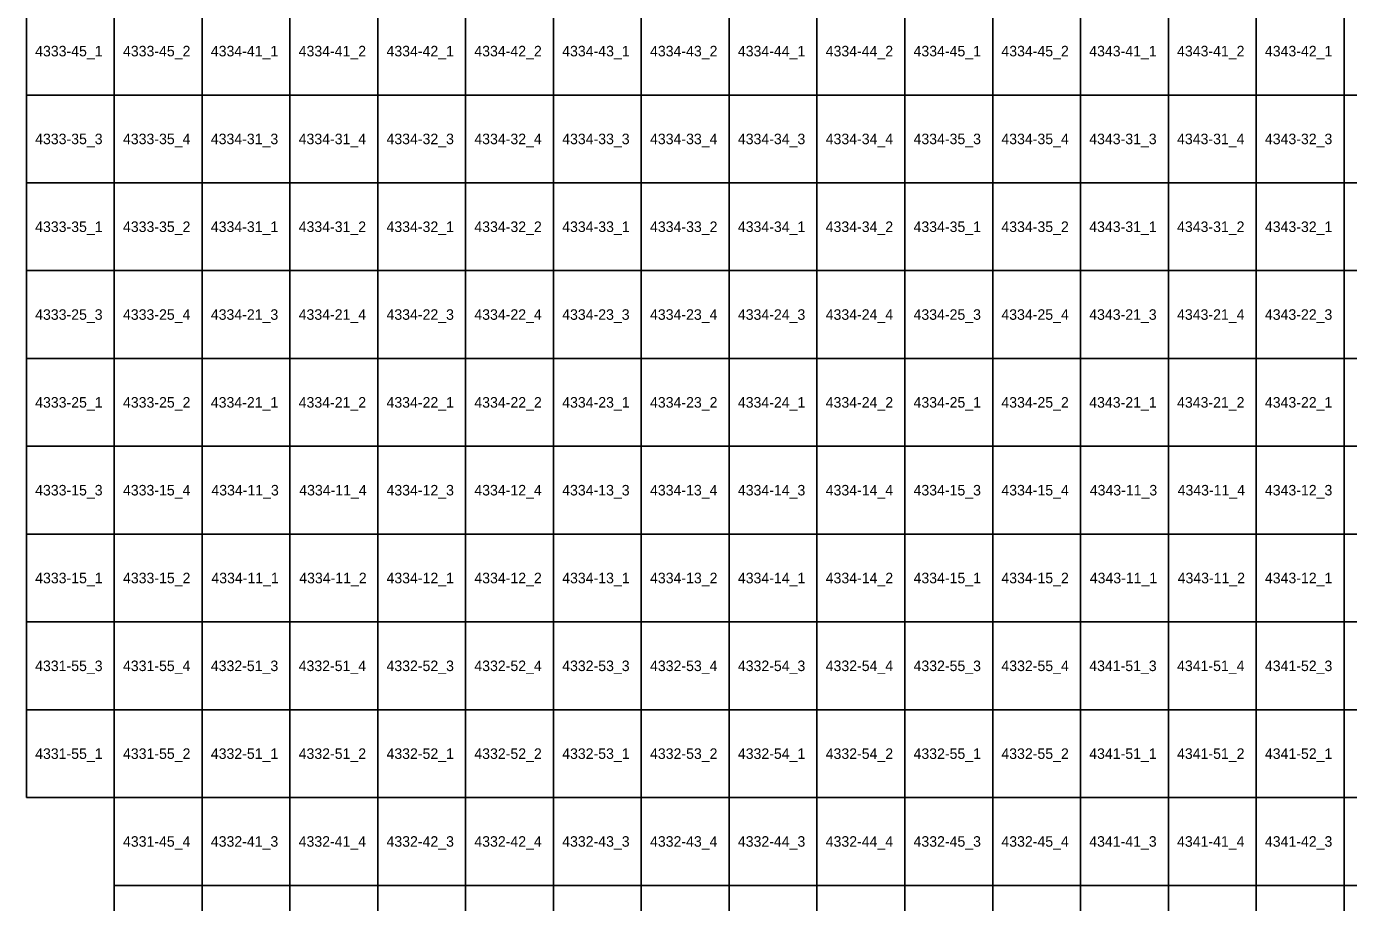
# Model space of a CAD drawing. Extents: x 312500 to 765000, y 172500 to 440000.
# Drawn here: x 520000 to 557629, y 367011 to 391952 of the extents above; entities that cross this region are included whole.
import ezdxf

# ---------------------------------------------------------------- set-up
doc = ezdxf.new("R2010")
doc.units = 0
doc.layers.add('Topo5_ramis_TKS2025', color=7, linetype='Continuous')
doc.layers.add('Topo5_ramis_TKS2025_Nr', color=7, linetype='Continuous')

msp = doc.modelspace()

# ---------------------------------------------------------------- linework, layer by layer
at = {"layer": 'Topo5_ramis_TKS2025'}
for points in [[(520000, 390000), (520000, 392500), (522500, 392500), (522500, 390000), (520000, 390000)], [(522500, 390000), (522500, 392500), (525000, 392500), (525000, 390000), (522500, 390000)], [(525000, 390000), (525000, 392500), (527500, 392500), (527500, 390000), (525000, 390000)], [(527500, 390000), (527500, 392500), (530000, 392500), (530000, 390000), (527500, 390000)], [(530000, 390000), (530000, 392500), (532500, 392500), (532500, 390000), (530000, 390000)], [(532500, 390000), (532500, 392500), (535000, 392500), (535000, 390000), (532500, 390000)], [(535000, 390000), (535000, 392500), (537500, 392500), (537500, 390000), (535000, 390000)], [(537500, 390000), (537500, 392500), (540000, 392500), (540000, 390000), (537500, 390000)], [(540000, 390000), (540000, 392500), (542500, 392500), (542500, 390000), (540000, 390000)], [(542500, 390000), (542500, 392500), (545000, 392500), (545000, 390000), (542500, 390000)], [(545000, 390000), (545000, 392500), (547500, 392500), (547500, 390000), (545000, 390000)], [(547500, 390000), (547500, 392500), (550000, 392500), (550000, 390000), (547500, 390000)], [(550000, 390000), (550000, 392500), (552500, 392500), (552500, 390000), (550000, 390000)], [(552500, 390000), (552500, 392500), (555000, 392500), (555000, 390000), (552500, 390000)], [(555000, 390000), (555000, 392500), (557500, 392500), (557500, 390000), (555000, 390000)], [(557500, 390000), (557500, 392500), (560000, 392500), (560000, 390000), (557500, 390000)], [(520000, 387500), (520000, 390000), (522500, 390000), (522500, 387500), (520000, 387500)], [(522500, 387500), (522500, 390000), (525000, 390000), (525000, 387500), (522500, 387500)], [(525000, 387500), (525000, 390000), (527500, 390000), (527500, 387500), (525000, 387500)], [(527500, 387500), (527500, 390000), (530000, 390000), (530000, 387500), (527500, 387500)], [(530000, 387500), (530000, 390000), (532500, 390000), (532500, 387500), (530000, 387500)], [(532500, 387500), (532500, 390000), (535000, 390000), (535000, 387500), (532500, 387500)], [(535000, 387500), (535000, 390000), (537500, 390000), (537500, 387500), (535000, 387500)], [(537500, 387500), (537500, 390000), (540000, 390000), (540000, 387500), (537500, 387500)], [(540000, 387500), (540000, 390000), (542500, 390000), (542500, 387500), (540000, 387500)], [(542500, 387500), (542500, 390000), (545000, 390000), (545000, 387500), (542500, 387500)], [(545000, 387500), (545000, 390000), (547500, 390000), (547500, 387500), (545000, 387500)], [(547500, 387500), (547500, 390000), (550000, 390000), (550000, 387500), (547500, 387500)], [(550000, 387500), (550000, 390000), (552500, 390000), (552500, 387500), (550000, 387500)], [(552500, 387500), (552500, 390000), (555000, 390000), (555000, 387500), (552500, 387500)], [(555000, 387500), (555000, 390000), (557500, 390000), (557500, 387500), (555000, 387500)], [(557500, 387500), (557500, 390000), (560000, 390000), (560000, 387500), (557500, 387500)], [(520000, 385000), (520000, 387500), (522500, 387500), (522500, 385000), (520000, 385000)], [(522500, 385000), (522500, 387500), (525000, 387500), (525000, 385000), (522500, 385000)], [(525000, 385000), (525000, 387500), (527500, 387500), (527500, 385000), (525000, 385000)], [(527500, 385000), (527500, 387500), (530000, 387500), (530000, 385000), (527500, 385000)], [(530000, 385000), (530000, 387500), (532500, 387500), (532500, 385000), (530000, 385000)], [(532500, 385000), (532500, 387500), (535000, 387500), (535000, 385000), (532500, 385000)], [(535000, 385000), (535000, 387500), (537500, 387500), (537500, 385000), (535000, 385000)], [(537500, 385000), (537500, 387500), (540000, 387500), (540000, 385000), (537500, 385000)], [(540000, 385000), (540000, 387500), (542500, 387500), (542500, 385000), (540000, 385000)], [(542500, 385000), (542500, 387500), (545000, 387500), (545000, 385000), (542500, 385000)], [(545000, 385000), (545000, 387500), (547500, 387500), (547500, 385000), (545000, 385000)], [(547500, 385000), (547500, 387500), (550000, 387500), (550000, 385000), (547500, 385000)], [(550000, 385000), (550000, 387500), (552500, 387500), (552500, 385000), (550000, 385000)], [(552500, 385000), (552500, 387500), (555000, 387500), (555000, 385000), (552500, 385000)], [(555000, 385000), (555000, 387500), (557500, 387500), (557500, 385000), (555000, 385000)], [(557500, 385000), (557500, 387500), (560000, 387500), (560000, 385000), (557500, 385000)], [(520000, 382500), (520000, 385000), (522500, 385000), (522500, 382500), (520000, 382500)], [(522500, 382500), (522500, 385000), (525000, 385000), (525000, 382500), (522500, 382500)], [(525000, 382500), (525000, 385000), (527500, 385000), (527500, 382500), (525000, 382500)], [(527500, 382500), (527500, 385000), (530000, 385000), (530000, 382500), (527500, 382500)], [(530000, 382500), (530000, 385000), (532500, 385000), (532500, 382500), (530000, 382500)], [(532500, 382500), (532500, 385000), (535000, 385000), (535000, 382500), (532500, 382500)], [(535000, 382500), (535000, 385000), (537500, 385000), (537500, 382500), (535000, 382500)], [(537500, 382500), (537500, 385000), (540000, 385000), (540000, 382500), (537500, 382500)], [(540000, 382500), (540000, 385000), (542500, 385000), (542500, 382500), (540000, 382500)], [(542500, 382500), (542500, 385000), (545000, 385000), (545000, 382500), (542500, 382500)], [(545000, 382500), (545000, 385000), (547500, 385000), (547500, 382500), (545000, 382500)], [(547500, 382500), (547500, 385000), (550000, 385000), (550000, 382500), (547500, 382500)], [(550000, 382500), (550000, 385000), (552500, 385000), (552500, 382500), (550000, 382500)], [(552500, 382500), (552500, 385000), (555000, 385000), (555000, 382500), (552500, 382500)], [(555000, 382500), (555000, 385000), (557500, 385000), (557500, 382500), (555000, 382500)], [(557500, 382500), (557500, 385000), (560000, 385000), (560000, 382500), (557500, 382500)], [(520000, 380000), (520000, 382500), (522500, 382500), (522500, 380000), (520000, 380000)], [(522500, 380000), (522500, 382500), (525000, 382500), (525000, 380000), (522500, 380000)], [(525000, 380000), (525000, 382500), (527500, 382500), (527500, 380000), (525000, 380000)], [(527500, 380000), (527500, 382500), (530000, 382500), (530000, 380000), (527500, 380000)], [(530000, 380000), (530000, 382500), (532500, 382500), (532500, 380000), (530000, 380000)], [(532500, 380000), (532500, 382500), (535000, 382500), (535000, 380000), (532500, 380000)], [(535000, 380000), (535000, 382500), (537500, 382500), (537500, 380000), (535000, 380000)], [(537500, 380000), (537500, 382500), (540000, 382500), (540000, 380000), (537500, 380000)], [(540000, 380000), (540000, 382500), (542500, 382500), (542500, 380000), (540000, 380000)], [(542500, 380000), (542500, 382500), (545000, 382500), (545000, 380000), (542500, 380000)], [(545000, 380000), (545000, 382500), (547500, 382500), (547500, 380000), (545000, 380000)], [(547500, 380000), (547500, 382500), (550000, 382500), (550000, 380000), (547500, 380000)], [(550000, 380000), (550000, 382500), (552500, 382500), (552500, 380000), (550000, 380000)], [(552500, 380000), (552500, 382500), (555000, 382500), (555000, 380000), (552500, 380000)], [(555000, 380000), (555000, 382500), (557500, 382500), (557500, 380000), (555000, 380000)], [(557500, 380000), (557500, 382500), (560000, 382500), (560000, 380000), (557500, 380000)], [(520000, 377500), (520000, 380000), (522500, 380000), (522500, 377500), (520000, 377500)], [(522500, 377500), (522500, 380000), (525000, 380000), (525000, 377500), (522500, 377500)], [(525000, 377500), (525000, 380000), (527500, 380000), (527500, 377500), (525000, 377500)], [(527500, 377500), (527500, 380000), (530000, 380000), (530000, 377500), (527500, 377500)], [(530000, 377500), (530000, 380000), (532500, 380000), (532500, 377500), (530000, 377500)], [(532500, 377500), (532500, 380000), (535000, 380000), (535000, 377500), (532500, 377500)], [(535000, 377500), (535000, 380000), (537500, 380000), (537500, 377500), (535000, 377500)], [(537500, 377500), (537500, 380000), (540000, 380000), (540000, 377500), (537500, 377500)], [(540000, 377500), (540000, 380000), (542500, 380000), (542500, 377500), (540000, 377500)], [(542500, 377500), (542500, 380000), (545000, 380000), (545000, 377500), (542500, 377500)], [(545000, 377500), (545000, 380000), (547500, 380000), (547500, 377500), (545000, 377500)], [(547500, 377500), (547500, 380000), (550000, 380000), (550000, 377500), (547500, 377500)], [(550000, 377500), (550000, 380000), (552500, 380000), (552500, 377500), (550000, 377500)], [(552500, 377500), (552500, 380000), (555000, 380000), (555000, 377500), (552500, 377500)], [(555000, 377500), (555000, 380000), (557500, 380000), (557500, 377500), (555000, 377500)], [(557500, 377500), (557500, 380000), (560000, 380000), (560000, 377500), (557500, 377500)], [(520000, 375000), (520000, 377500), (522500, 377500), (522500, 375000), (520000, 375000)], [(522500, 375000), (522500, 377500), (525000, 377500), (525000, 375000), (522500, 375000)], [(525000, 375000), (525000, 377500), (527500, 377500), (527500, 375000), (525000, 375000)], [(527500, 375000), (527500, 377500), (530000, 377500), (530000, 375000), (527500, 375000)], [(530000, 375000), (530000, 377500), (532500, 377500), (532500, 375000), (530000, 375000)], [(532500, 375000), (532500, 377500), (535000, 377500), (535000, 375000), (532500, 375000)], [(535000, 375000), (535000, 377500), (537500, 377500), (537500, 375000), (535000, 375000)], [(537500, 375000), (537500, 377500), (540000, 377500), (540000, 375000), (537500, 375000)], [(540000, 375000), (540000, 377500), (542500, 377500), (542500, 375000), (540000, 375000)], [(542500, 375000), (542500, 377500), (545000, 377500), (545000, 375000), (542500, 375000)], [(545000, 375000), (545000, 377500), (547500, 377500), (547500, 375000), (545000, 375000)], [(547500, 375000), (547500, 377500), (550000, 377500), (550000, 375000), (547500, 375000)], [(550000, 375000), (550000, 377500), (552500, 377500), (552500, 375000), (550000, 375000)], [(552500, 375000), (552500, 377500), (555000, 377500), (555000, 375000), (552500, 375000)], [(555000, 375000), (555000, 377500), (557500, 377500), (557500, 375000), (555000, 375000)], [(557500, 375000), (557500, 377500), (560000, 377500), (560000, 375000), (557500, 375000)], [(520000, 372500), (520000, 375000), (522500, 375000), (522500, 372500), (520000, 372500)], [(522500, 372500), (522500, 375000), (525000, 375000), (525000, 372500), (522500, 372500)], [(525000, 372500), (525000, 375000), (527500, 375000), (527500, 372500), (525000, 372500)], [(527500, 372500), (527500, 375000), (530000, 375000), (530000, 372500), (527500, 372500)], [(530000, 372500), (530000, 375000), (532500, 375000), (532500, 372500), (530000, 372500)], [(532500, 372500), (532500, 375000), (535000, 375000), (535000, 372500), (532500, 372500)], [(535000, 372500), (535000, 375000), (537500, 375000), (537500, 372500), (535000, 372500)], [(537500, 372500), (537500, 375000), (540000, 375000), (540000, 372500), (537500, 372500)], [(540000, 372500), (540000, 375000), (542500, 375000), (542500, 372500), (540000, 372500)], [(542500, 372500), (542500, 375000), (545000, 375000), (545000, 372500), (542500, 372500)], [(545000, 372500), (545000, 375000), (547500, 375000), (547500, 372500), (545000, 372500)], [(547500, 372500), (547500, 375000), (550000, 375000), (550000, 372500), (547500, 372500)], [(550000, 372500), (550000, 375000), (552500, 375000), (552500, 372500), (550000, 372500)], [(552500, 372500), (552500, 375000), (555000, 375000), (555000, 372500), (552500, 372500)], [(555000, 372500), (555000, 375000), (557500, 375000), (557500, 372500), (555000, 372500)], [(557500, 372500), (557500, 375000), (560000, 375000), (560000, 372500), (557500, 372500)], [(520000, 370000), (520000, 372500), (522500, 372500), (522500, 370000), (520000, 370000)], [(522500, 370000), (522500, 372500), (525000, 372500), (525000, 370000), (522500, 370000)], [(525000, 370000), (525000, 372500), (527500, 372500), (527500, 370000), (525000, 370000)], [(527500, 370000), (527500, 372500), (530000, 372500), (530000, 370000), (527500, 370000)], [(530000, 370000), (530000, 372500), (532500, 372500), (532500, 370000), (530000, 370000)], [(532500, 370000), (532500, 372500), (535000, 372500), (535000, 370000), (532500, 370000)], [(535000, 370000), (535000, 372500), (537500, 372500), (537500, 370000), (535000, 370000)], [(537500, 370000), (537500, 372500), (540000, 372500), (540000, 370000), (537500, 370000)], [(540000, 370000), (540000, 372500), (542500, 372500), (542500, 370000), (540000, 370000)], [(542500, 370000), (542500, 372500), (545000, 372500), (545000, 370000), (542500, 370000)], [(545000, 370000), (545000, 372500), (547500, 372500), (547500, 370000), (545000, 370000)], [(547500, 370000), (547500, 372500), (550000, 372500), (550000, 370000), (547500, 370000)], [(550000, 370000), (550000, 372500), (552500, 372500), (552500, 370000), (550000, 370000)], [(552500, 370000), (552500, 372500), (555000, 372500), (555000, 370000), (552500, 370000)], [(555000, 370000), (555000, 372500), (557500, 372500), (557500, 370000), (555000, 370000)], [(557500, 370000), (557500, 372500), (560000, 372500), (560000, 370000), (557500, 370000)], [(522500, 367500), (522500, 370000), (525000, 370000), (525000, 367500), (522500, 367500)], [(525000, 367500), (525000, 370000), (527500, 370000), (527500, 367500), (525000, 367500)], [(527500, 367500), (527500, 370000), (530000, 370000), (530000, 367500), (527500, 367500)], [(530000, 367500), (530000, 370000), (532500, 370000), (532500, 367500), (530000, 367500)], [(532500, 367500), (532500, 370000), (535000, 370000), (535000, 367500), (532500, 367500)], [(535000, 367500), (535000, 370000), (537500, 370000), (537500, 367500), (535000, 367500)], [(537500, 367500), (537500, 370000), (540000, 370000), (540000, 367500), (537500, 367500)], [(540000, 367500), (540000, 370000), (542500, 370000), (542500, 367500), (540000, 367500)], [(542500, 367500), (542500, 370000), (545000, 370000), (545000, 367500), (542500, 367500)], [(545000, 367500), (545000, 370000), (547500, 370000), (547500, 367500), (545000, 367500)], [(547500, 367500), (547500, 370000), (550000, 370000), (550000, 367500), (547500, 367500)], [(550000, 367500), (550000, 370000), (552500, 370000), (552500, 367500), (550000, 367500)], [(552500, 367500), (552500, 370000), (555000, 370000), (555000, 367500), (552500, 367500)], [(555000, 367500), (555000, 370000), (557500, 370000), (557500, 367500), (555000, 367500)], [(557500, 367500), (557500, 370000), (560000, 370000), (560000, 367500), (557500, 367500)], [(522500, 365000), (522500, 367500), (525000, 367500), (525000, 365000), (522500, 365000)], [(525000, 365000), (525000, 367500), (527500, 367500), (527500, 365000), (525000, 365000)], [(527500, 365000), (527500, 367500), (530000, 367500), (530000, 365000), (527500, 365000)], [(530000, 365000), (530000, 367500), (532500, 367500), (532500, 365000), (530000, 365000)], [(532500, 365000), (532500, 367500), (535000, 367500), (535000, 365000), (532500, 365000)], [(535000, 365000), (535000, 367500), (537500, 367500), (537500, 365000), (535000, 365000)], [(537500, 365000), (537500, 367500), (540000, 367500), (540000, 365000), (537500, 365000)], [(540000, 365000), (540000, 367500), (542500, 367500), (542500, 365000), (540000, 365000)], [(542500, 365000), (542500, 367500), (545000, 367500), (545000, 365000), (542500, 365000)], [(545000, 365000), (545000, 367500), (547500, 367500), (547500, 365000), (545000, 365000)], [(547500, 365000), (547500, 367500), (550000, 367500), (550000, 365000), (547500, 365000)], [(550000, 365000), (550000, 367500), (552500, 367500), (552500, 365000), (550000, 365000)], [(552500, 365000), (552500, 367500), (555000, 367500), (555000, 365000), (552500, 365000)], [(555000, 365000), (555000, 367500), (557500, 367500), (557500, 365000), (555000, 365000)], [(557500, 365000), (557500, 367500), (560000, 367500), (560000, 365000), (557500, 365000)]]:
    msp.add_lwpolyline(points, dxfattribs=at)

# ---------------------------------------------------------------- texts
at = {"layer": 'Topo5_ramis_TKS2025_Nr'}
for s, p in [('4333-45_1', (520248, 391100)), ('4333-45_2', (522748, 391100)), ('4334-41_1', (525248, 391100)), ('4334-41_2', (527748, 391100)), ('4334-42_1', (530248, 391100)), ('4334-42_2', (532748, 391100)), ('4334-43_1', (535248, 391100)), ('4334-43_2', (537748, 391100)), ('4334-44_1', (540248, 391100)), ('4334-44_2', (542748, 391100)), ('4334-45_1', (545248, 391100)), ('4334-45_2', (547748, 391100)), ('4343-41_1', (550248, 391100)), ('4343-41_2', (552748, 391100)), ('4343-42_1', (555248, 391100)), ('4333-35_3', (520248, 388600)), ('4333-35_4', (522748, 388600)), ('4334-31_3', (525248, 388600)), ('4334-31_4', (527748, 388600)), ('4334-32_3', (530248, 388600)), ('4334-32_4', (532748, 388600)), ('4334-33_3', (535248, 388600)), ('4334-33_4', (537748, 388600)), ('4334-34_3', (540248, 388600)), ('4334-34_4', (542748, 388600)), ('4334-35_3', (545248, 388600)), ('4334-35_4', (547748, 388600)), ('4343-31_3', (550248, 388600)), ('4343-31_4', (552748, 388600)), ('4343-32_3', (555248, 388600)), ('4333-35_1', (520248, 386100)), ('4333-35_2', (522748, 386100)), ('4334-31_1', (525248, 386100)), ('4334-31_2', (527748, 386100)), ('4334-32_1', (530248, 386100)), ('4334-32_2', (532748, 386100)), ('4334-33_1', (535248, 386100)), ('4334-33_2', (537748, 386100)), ('4334-34_1', (540248, 386100)), ('4334-34_2', (542748, 386100)), ('4334-35_1', (545248, 386100)), ('4334-35_2', (547748, 386100)), ('4343-31_1', (550248, 386100)), ('4343-31_2', (552748, 386100)), ('4343-32_1', (555248, 386100)), ('4333-25_3', (520248, 383600)), ('4333-25_4', (522748, 383600)), ('4334-21_3', (525248, 383600)), ('4334-21_4', (527748, 383600)), ('4334-22_3', (530248, 383600)), ('4334-22_4', (532748, 383600)), ('4334-23_3', (535248, 383600)), ('4334-23_4', (537748, 383600)), ('4334-24_3', (540248, 383600)), ('4334-24_4', (542748, 383600)), ('4334-25_3', (545248, 383600)), ('4334-25_4', (547748, 383600)), ('4343-21_3', (550248, 383600)), ('4343-21_4', (552748, 383600)), ('4343-22_3', (555248, 383600)), ('4333-25_1', (520248, 381100)), ('4333-25_2', (522748, 381100)), ('4334-21_1', (525248, 381100)), ('4334-21_2', (527748, 381100)), ('4334-22_1', (530248, 381100)), ('4334-22_2', (532748, 381100)), ('4334-23_1', (535248, 381100)), ('4334-23_2', (537748, 381100)), ('4334-24_1', (540248, 381100)), ('4334-24_2', (542748, 381100)), ('4334-25_1', (545248, 381100)), ('4334-25_2', (547748, 381100)), ('4343-21_1', (550248, 381100)), ('4343-21_2', (552748, 381100)), ('4343-22_1', (555248, 381100)), ('4333-15_3', (520248, 378600)), ('4333-15_4', (522748, 378600)), ('4334-11_3', (525264, 378600)), ('4334-11_4', (527764, 378600)), ('4334-12_3', (530248, 378600)), ('4334-12_4', (532748, 378600)), ('4334-13_3', (535248, 378600)), ('4334-13_4', (537748, 378600)), ('4334-14_3', (540248, 378600)), ('4334-14_4', (542748, 378600)), ('4334-15_3', (545248, 378600)), ('4334-15_4', (547748, 378600)), ('4343-11_3', (550264, 378600)), ('4343-11_4', (552764, 378600)), ('4343-12_3', (555248, 378600)), ('4333-15_1', (520248, 376100)), ('4333-15_2', (522748, 376100)), ('4334-11_1', (525264, 376100)), ('4334-11_2', (527764, 376100)), ('4334-12_1', (530248, 376100)), ('4334-12_2', (532748, 376100)), ('4334-13_1', (535248, 376100)), ('4334-13_2', (537748, 376100)), ('4334-14_1', (540248, 376100)), ('4334-14_2', (542748, 376100)), ('4334-15_1', (545248, 376100)), ('4334-15_2', (547748, 376100)), ('4343-11_1', (550264, 376100)), ('4343-11_2', (552764, 376100)), ('4343-12_1', (555248, 376100)), ('4331-55_3', (520248, 373600)), ('4331-55_4', (522748, 373600)), ('4332-51_3', (525248, 373600)), ('4332-51_4', (527748, 373600)), ('4332-52_3', (530248, 373600)), ('4332-52_4', (532748, 373600)), ('4332-53_3', (535248, 373600)), ('4332-53_4', (537748, 373600)), ('4332-54_3', (540248, 373600)), ('4332-54_4', (542748, 373600)), ('4332-55_3', (545248, 373600)), ('4332-55_4', (547748, 373600)), ('4341-51_3', (550248, 373600)), ('4341-51_4', (552748, 373600)), ('4341-52_3', (555248, 373600)), ('4331-55_1', (520248, 371100)), ('4331-55_2', (522748, 371100)), ('4332-51_1', (525248, 371100)), ('4332-51_2', (527748, 371100)), ('4332-52_1', (530248, 371100)), ('4332-52_2', (532748, 371100)), ('4332-53_1', (535248, 371100)), ('4332-53_2', (537748, 371100)), ('4332-54_1', (540248, 371100)), ('4332-54_2', (542748, 371100)), ('4332-55_1', (545248, 371100)), ('4332-55_2', (547748, 371100)), ('4341-51_1', (550248, 371100)), ('4341-51_2', (552748, 371100)), ('4341-52_1', (555248, 371100)), ('4331-45_4', (522748, 368600)), ('4332-41_3', (525248, 368600)), ('4332-41_4', (527748, 368600)), ('4332-42_3', (530248, 368600)), ('4332-42_4', (532748, 368600)), ('4332-43_3', (535248, 368600)), ('4332-43_4', (537748, 368600)), ('4332-44_3', (540248, 368600)), ('4332-44_4', (542748, 368600)), ('4332-45_3', (545248, 368600)), ('4332-45_4', (547748, 368600)), ('4341-41_3', (550248, 368600)), ('4341-41_4', (552748, 368600)), ('4341-42_3', (555248, 368600))]:
    msp.add_text(s, height=300, dxfattribs=at).set_placement(p)

doc.saveas('drawing.dxf')
